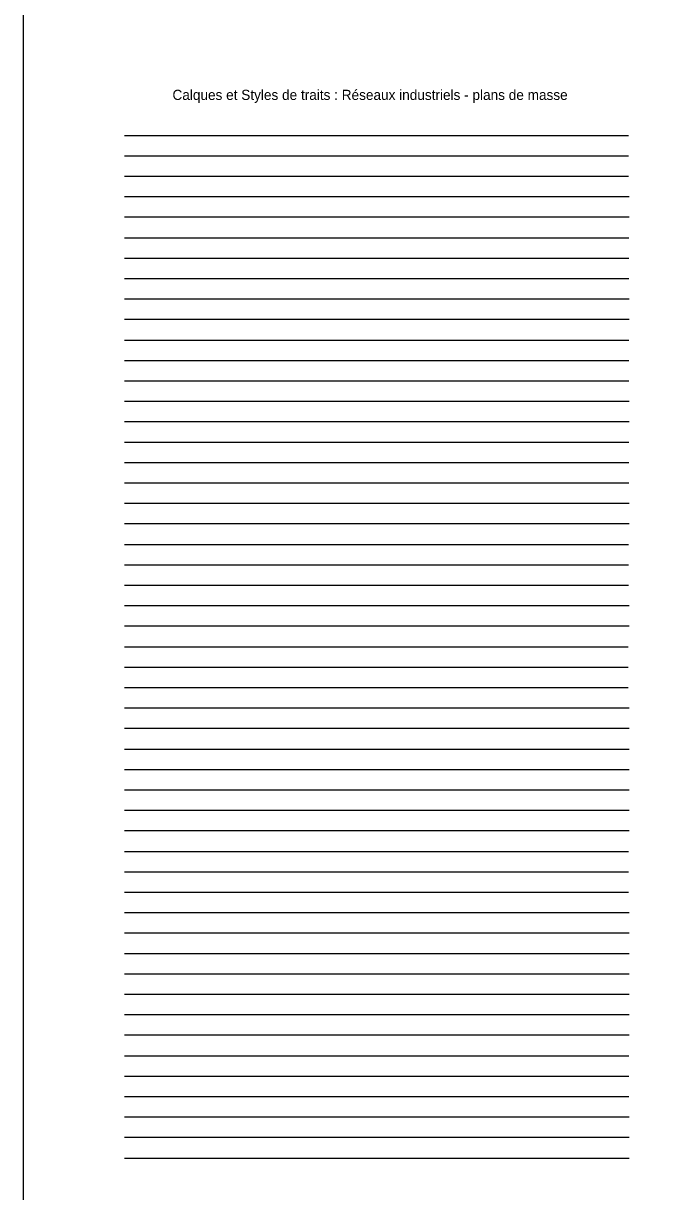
# Model space of a CAD drawing. Extents: x 703432 to 707394, y 7057985 to 7059523.
# Drawn here: x 707199.5 to 707230.6, y 7058477 to 7058534.5 of the extents above; entities that cross this region are included whole.
import ezdxf

# ---------------------------------------------------------------- set-up
doc = ezdxf.new("R2010")
doc.units = 0
for name, color, linetype in [('DH_CADRE -CARTOUCHE', 7, 'Continuous'), ('R_IND_ACETYLENE_CANALISATION_CL_A', 7, 'Continuous'), ('R_IND_ACETYLENE_CANALISATION_CL_B', 7, 'Continuous'), ('R_IND_ACETYLENE_CANALISATION_CL_C', 7, 'Continuous'), ('R_IND_ACETYLENE_EQUIP', 7, 'Continuous'), ('R_IND_ACETYLENE_TEXTE', 7, 'Continuous'), ('R_IND_AIR_BP_CANALISATION_CL_A', 7, 'Continuous'), ('R_IND_AIR_BP_CANALISATION_CL_B', 7, 'Continuous'), ('R_IND_AIR_BP_CANALISATION_CL_C', 7, 'Continuous'), ('R_IND_AIR_BP_EQUIP', 7, 'Continuous'), ('R_IND_AIR_BP_TEXTE', 7, 'Continuous'), ('R_IND_AIR_HP_CANALISATION_CL_A', 7, 'Continuous'), ('R_IND_AIR_HP_CANALISATION_CL_B', 7, 'Continuous'), ('R_IND_AIR_HP_CANALISATION_CL_C', 7, 'Continuous'), ('R_IND_AIR_HP_EQUIP', 7, 'Continuous'), ('R_IND_AIR_HP_TEXTE', 7, 'Continuous'), ('R_IND_ALT_POINT', 7, 'Continuous'), ('R_IND_AZOTE_CANALISATION_CL_A', 7, 'Continuous'), ('R_IND_AZOTE_CANALISATION_CL_B', 7, 'Continuous'), ('R_IND_AZOTE_CANALISATION_CL_C', 7, 'Continuous'), ('R_IND_AZOTE_EQUIP', 7, 'Continuous'), ('R_IND_AZOTE_TEXTE', 7, 'Continuous'), ('R_IND_EAU_DEMINERALISEE_CANALISATION_CL_A', 7, 'Continuous'), ('R_IND_EAU_DEMINERALISEE_CANALISATION_CL_B', 7, 'Continuous'), ('R_IND_EAU_DEMINERALISEE_CANALISATION_CL_C', 7, 'Continuous'), ('R_IND_EAU_DEMINERALISEE_EQUIP', 7, 'Continuous'), ('R_IND_EAU_DEMINERALISEE_TEXTE', 7, 'Continuous'), ('R_IND_GAZ_NAT_CANALISATION_CL_A', 7, 'Continuous'), ('R_IND_GAZ_NAT_CANALISATION_CL_B', 7, 'Continuous'), ('R_IND_GAZ_NAT_CANALISATION_CL_C', 7, 'Continuous'), ('R_IND_GAZ_NAT_EQUIP', 7, 'Continuous'), ('R_IND_GAZ_NAT_TEXTE', 7, 'Continuous'), ('R_IND_HYDROCARBURE_CANALISATION_CL_A', 7, 'Continuous'), ('R_IND_HYDROCARBURE_CANALISATION_CL_B', 7, 'Continuous'), ('R_IND_HYDROCARBURE_CANALISATION_CL_C', 7, 'Continuous'), ('R_IND_HYDROCARBURE_EQUIP', 7, 'Continuous'), ('R_IND_HYDROCARBURE_TEXTE', 7, 'Continuous'), ('R_IND_INDUS_INCON_CANALISATION_CL_A', 7, 'Continuous'), ('R_IND_INDUS_INCON_CANALISATION_CL_B', 7, 'Continuous'), ('R_IND_INDUS_INCON_CANALISATION_CL_C', 7, 'Continuous'), ('R_IND_INDUS_INCON_EQUIP', 7, 'Continuous'), ('R_IND_INDUS_INCON_TEXTE', 7, 'Continuous'), ('R_IND_OXYGENE_CANALISATION_CL_A', 7, 'Continuous'), ('R_IND_OXYGENE_CANALISATION_CL_B', 7, 'Continuous'), ('R_IND_OXYGENE_CANALISATION_CL_C', 7, 'Continuous'), ('R_IND_OXYGENE_EQUIP', 7, 'Continuous'), ('R_IND_OXYGENE_TEXTE', 7, 'Continuous'), ('R_IND_PROPANE_CANALISATION_CL_A', 7, 'Continuous'), ('R_IND_PROPANE_CANALISATION_CL_B', 7, 'Continuous'), ('R_IND_PROPANE_CANALISATION_CL_C', 7, 'Continuous'), ('R_IND_PROPANE_EQUIP', 7, 'Continuous'), ('R_IND_PROPANE_TEXTE', 7, 'Continuous')]:
    doc.layers.add(name, color=color, linetype=linetype)

msp = doc.modelspace()

# ---------------------------------------------------------------- linework, layer by layer
at = {"layer": 'DH_CADRE -CARTOUCHE'}
msp.add_lwpolyline([(707199.469, 7058644.551), (707324.469, 7058644.551), (707324.469, 7058419.551), (707199.469, 7058419.551)], close=True, dxfattribs=at)
at = {"layer": 'R_IND_ACETYLENE_CANALISATION_CL_A'}
msp.add_line((707204.439, 7058503.825), (707229.21, 7058503.825), dxfattribs=at)
at = {"layer": 'R_IND_ACETYLENE_CANALISATION_CL_B'}
msp.add_line((707204.439, 7058502.825), (707229.21, 7058502.825), dxfattribs=at)
at = {"layer": 'R_IND_ACETYLENE_CANALISATION_CL_C'}
msp.add_line((707204.439, 7058501.825), (707229.21, 7058501.825), dxfattribs=at)
at = {"layer": 'R_IND_ACETYLENE_EQUIP'}
msp.add_line((707204.439, 7058500.825), (707229.269, 7058500.825), dxfattribs=at)
at = {"layer": 'R_IND_ACETYLENE_TEXTE'}
msp.add_line((707204.439, 7058499.825), (707229.269, 7058499.825), dxfattribs=at)
at = {"layer": 'R_IND_AIR_BP_CANALISATION_CL_A'}
msp.add_line((707204.439, 7058528.98), (707229.225, 7058528.98), dxfattribs=at)
at = {"layer": 'R_IND_AIR_BP_CANALISATION_CL_B'}
msp.add_line((707204.439, 7058527.98), (707229.225, 7058527.98), dxfattribs=at)
at = {"layer": 'R_IND_AIR_BP_CANALISATION_CL_C'}
msp.add_line((707204.439, 7058526.98), (707229.225, 7058526.98), dxfattribs=at)
at = {"layer": 'R_IND_AIR_BP_EQUIP'}
msp.add_line((707204.439, 7058525.98), (707229.269, 7058525.98), dxfattribs=at)
at = {"layer": 'R_IND_AIR_BP_TEXTE'}
msp.add_line((707204.439, 7058524.98), (707229.269, 7058524.98), dxfattribs=at)
at = {"layer": 'R_IND_AIR_HP_CANALISATION_CL_A'}
msp.add_line((707204.439, 7058523.949), (707229.24, 7058523.949), dxfattribs=at)
at = {"layer": 'R_IND_AIR_HP_CANALISATION_CL_B'}
msp.add_line((707204.439, 7058522.949), (707229.24, 7058522.949), dxfattribs=at)
at = {"layer": 'R_IND_AIR_HP_CANALISATION_CL_C'}
msp.add_line((707204.439, 7058521.949), (707229.24, 7058521.949), dxfattribs=at)
at = {"layer": 'R_IND_AIR_HP_EQUIP'}
msp.add_line((707204.439, 7058520.949), (707229.269, 7058520.949), dxfattribs=at)
at = {"layer": 'R_IND_AIR_HP_TEXTE'}
msp.add_line((707204.439, 7058519.949), (707229.269, 7058519.949), dxfattribs=at)
at = {"layer": 'R_IND_ALT_POINT'}
msp.add_line((707204.439, 7058478.67), (707229.269, 7058478.67), dxfattribs=at)
at = {"layer": 'R_IND_AZOTE_CANALISATION_CL_A'}
msp.add_line((707204.439, 7058513.887), (707229.24, 7058513.887), dxfattribs=at)
at = {"layer": 'R_IND_AZOTE_CANALISATION_CL_B'}
msp.add_line((707204.439, 7058512.887), (707229.24, 7058512.887), dxfattribs=at)
at = {"layer": 'R_IND_AZOTE_CANALISATION_CL_C'}
msp.add_line((707204.439, 7058511.887), (707229.24, 7058511.887), dxfattribs=at)
at = {"layer": 'R_IND_AZOTE_EQUIP'}
msp.add_line((707204.439, 7058510.887), (707229.269, 7058510.887), dxfattribs=at)
at = {"layer": 'R_IND_AZOTE_TEXTE'}
msp.add_line((707204.439, 7058509.887), (707229.269, 7058509.887), dxfattribs=at)
at = {"layer": 'R_IND_EAU_DEMINERALISEE_CANALISATION_CL_A'}
msp.add_line((707204.439, 7058483.701), (707229.24, 7058483.701), dxfattribs=at)
at = {"layer": 'R_IND_EAU_DEMINERALISEE_CANALISATION_CL_B'}
msp.add_line((707204.439, 7058482.701), (707229.24, 7058482.701), dxfattribs=at)
at = {"layer": 'R_IND_EAU_DEMINERALISEE_CANALISATION_CL_C'}
msp.add_line((707204.439, 7058481.701), (707229.24, 7058481.701), dxfattribs=at)
at = {"layer": 'R_IND_EAU_DEMINERALISEE_EQUIP'}
msp.add_line((707204.439, 7058480.701), (707229.269, 7058480.701), dxfattribs=at)
at = {"layer": 'R_IND_EAU_DEMINERALISEE_TEXTE'}
msp.add_line((707204.439, 7058479.701), (707229.269, 7058479.701), dxfattribs=at)
at = {"layer": 'R_IND_GAZ_NAT_CANALISATION_CL_A'}
msp.add_line((707204.439, 7058518.918), (707229.24, 7058518.918), dxfattribs=at)
at = {"layer": 'R_IND_GAZ_NAT_CANALISATION_CL_B'}
msp.add_line((707204.439, 7058517.918), (707229.24, 7058517.918), dxfattribs=at)
at = {"layer": 'R_IND_GAZ_NAT_CANALISATION_CL_C'}
msp.add_line((707204.439, 7058516.918), (707229.24, 7058516.918), dxfattribs=at)
at = {"layer": 'R_IND_GAZ_NAT_EQUIP'}
msp.add_line((707204.439, 7058515.918), (707229.269, 7058515.918), dxfattribs=at)
at = {"layer": 'R_IND_GAZ_NAT_TEXTE'}
msp.add_line((707204.439, 7058514.918), (707229.269, 7058514.918), dxfattribs=at)
at = {"layer": 'R_IND_HYDROCARBURE_CANALISATION_CL_A'}
msp.add_line((707204.439, 7058498.794), (707229.254, 7058498.794), dxfattribs=at)
at = {"layer": 'R_IND_HYDROCARBURE_CANALISATION_CL_B'}
msp.add_line((707204.439, 7058497.794), (707229.254, 7058497.794), dxfattribs=at)
at = {"layer": 'R_IND_HYDROCARBURE_CANALISATION_CL_C'}
msp.add_line((707204.439, 7058496.794), (707229.254, 7058496.794), dxfattribs=at)
at = {"layer": 'R_IND_HYDROCARBURE_EQUIP'}
msp.add_line((707204.439, 7058495.794), (707229.269, 7058495.794), dxfattribs=at)
at = {"layer": 'R_IND_HYDROCARBURE_TEXTE'}
msp.add_line((707204.439, 7058494.794), (707229.269, 7058494.794), dxfattribs=at)
at = {"layer": 'R_IND_INDUS_INCON_CANALISATION_CL_A'}
msp.add_line((707204.439, 7058488.732), (707229.254, 7058488.732), dxfattribs=at)
at = {"layer": 'R_IND_INDUS_INCON_CANALISATION_CL_B'}
msp.add_line((707204.439, 7058487.732), (707229.254, 7058487.732), dxfattribs=at)
at = {"layer": 'R_IND_INDUS_INCON_CANALISATION_CL_C'}
msp.add_line((707204.439, 7058486.732), (707229.254, 7058486.732), dxfattribs=at)
at = {"layer": 'R_IND_INDUS_INCON_EQUIP'}
msp.add_line((707204.439, 7058485.732), (707229.269, 7058485.732), dxfattribs=at)
at = {"layer": 'R_IND_INDUS_INCON_TEXTE'}
msp.add_line((707204.439, 7058484.732), (707229.269, 7058484.732), dxfattribs=at)
at = {"layer": 'R_IND_OXYGENE_CANALISATION_CL_A'}
msp.add_line((707204.439, 7058508.856), (707229.225, 7058508.856), dxfattribs=at)
at = {"layer": 'R_IND_OXYGENE_CANALISATION_CL_B'}
msp.add_line((707204.439, 7058507.856), (707229.225, 7058507.856), dxfattribs=at)
at = {"layer": 'R_IND_OXYGENE_CANALISATION_CL_C'}
msp.add_line((707204.439, 7058506.856), (707229.225, 7058506.856), dxfattribs=at)
at = {"layer": 'R_IND_OXYGENE_EQUIP'}
msp.add_line((707204.439, 7058505.856), (707229.269, 7058505.856), dxfattribs=at)
at = {"layer": 'R_IND_OXYGENE_TEXTE'}
msp.add_line((707204.439, 7058504.856), (707229.269, 7058504.856), dxfattribs=at)
at = {"layer": 'R_IND_PROPANE_CANALISATION_CL_A'}
msp.add_line((707204.439, 7058493.763), (707229.225, 7058493.763), dxfattribs=at)
at = {"layer": 'R_IND_PROPANE_CANALISATION_CL_B'}
msp.add_line((707204.439, 7058492.763), (707229.225, 7058492.763), dxfattribs=at)
at = {"layer": 'R_IND_PROPANE_CANALISATION_CL_C'}
msp.add_line((707204.439, 7058491.763), (707229.225, 7058491.763), dxfattribs=at)
at = {"layer": 'R_IND_PROPANE_EQUIP'}
msp.add_line((707204.439, 7058490.763), (707229.269, 7058490.763), dxfattribs=at)
at = {"layer": 'R_IND_PROPANE_TEXTE'}
msp.add_line((707204.439, 7058489.763), (707229.269, 7058489.763), dxfattribs=at)

# ---------------------------------------------------------------- texts
at = {"layer": 'DH_CADRE -CARTOUCHE'}
msp.add_text(' Calques et Styles de traits : Réseaux industriels - plans de masse', height=0.5, dxfattribs=at).set_placement((707206.616, 7058530.73))

doc.saveas('drawing.dxf')
